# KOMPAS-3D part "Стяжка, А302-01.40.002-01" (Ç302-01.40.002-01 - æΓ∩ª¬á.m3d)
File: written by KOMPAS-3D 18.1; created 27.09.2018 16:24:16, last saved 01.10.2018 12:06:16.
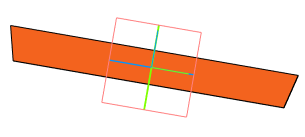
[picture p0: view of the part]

Document properties: Автор: Милов; Полное имя файла: D:\Мембранные насосы\Мембранный электропривод\А302-00.00.000 - ASTRA-302 (МЭ200)\3Д ПВХ\Отработка\А302-01.40.002-01 - Стяжка.m3d

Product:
- Part/product: Стяжка  | designation А302-01.40.002-01
    Масса: 0.219609
    Раздел спецификации: Детали
    Форматы листов документа: A4

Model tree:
1. Эскиз:1
2. Операция выдавливания:1
     Расстояние 2 = 10
3. Эскиз:2  (with: Операция выдавливания:1)
4. Вырезать элемент выдавливания:1
     Расстояние 1 = 20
